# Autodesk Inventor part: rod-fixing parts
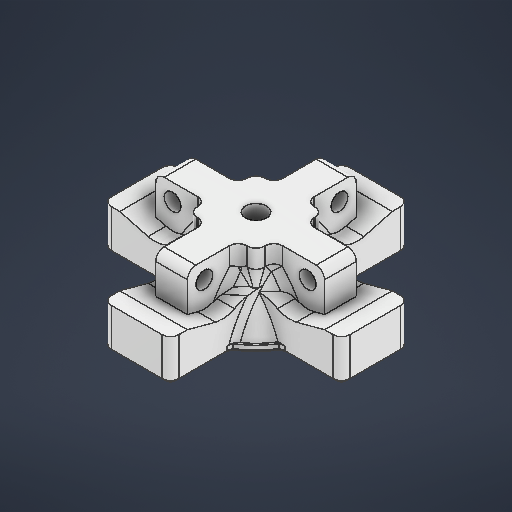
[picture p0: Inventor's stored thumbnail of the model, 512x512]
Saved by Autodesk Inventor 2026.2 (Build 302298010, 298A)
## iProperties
Created: 2026-05
Part Number: rod-fixing parts
Material: ABS 플라스틱
Document SubType Name: Modeling
Designer: work
Density: 1.06 g/cm^3
Appearance: 매끄러움 - 흰색
Author: work
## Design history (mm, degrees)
sketch "스케치1"
  geometry: L1 (-8, 8)-(8, 8); L2 (8, 8)-(8, -8); L3 (8, -8)-(-8, -8); L4 (-8, -8)-(-8, 8); L5 (-8, 8)-(8, -8); L6 (8, 8)-(-8, -8); L7 (-3.75, 20)-(3.75, 20); L8 (3.75, 20)-(3.75, -20); L9 (3.75, -20)-(-3.75, -20); L10 (-3.75, -20)-(-3.75, 20); L11 (-3.75, 20)-(3.75, -20); L12 (3.75, 20)-(-3.75, -20); C1 r 2.5 at (0, 0); 5 further points
  constraints: 24 end point, 4 midpoint, 4 parallel, 2 horizontal, 2 perpendicular, 1 centre point, 1 coincident
  dimensions: "d0" = 16 distance of L2.end L3.end; "d1" = 16 distance of L1.end L2.end; "d2" = 5 diameter of C1; "d3" = 12 distance between parallel lines of L9 L3; "d4" = 7.5 distance of L8.end L9.end
extrude "돌출1" new body sketch "스케치1" distance "d5" = 8; taper "d6" = 0 deg
sketch "스케치2"
  geometry: L1 (0, 0)-(12, 0) reference; L2 (12, 0)-(12, 8) reference; L3 (0, 8)-(12, 8) reference; L4 (0, 0)-(0, 8) reference; L5 (28, 0)-(40, 0) reference; L6 (40, 0)-(40, 8) reference; L7 (28, 8)-(40, 8) reference; L8 (28, 0)-(28, 8) reference; L9 (40, 0)-(40, 8) reference; L10 (40, 4)-(28, 4); L11 (12, 4)-(0, 4); C1 r 2 at (4, 4); C2 r 2 at (36, 4); 1 further point
  constraints: 4 end point, 4 midpoint, 2 centre point, 2 point on line
  dimensions: "d7" = 4 diameter of C2; "d8" = 4 distance from line of L6 C2.centre; "d9" = 4 distance from line of L4 C1.centre; "d10" = 4 diameter of C1
extrude "돌출2" cut sketch "스케치2" extent not by distance; stored distance "d11" = 0; taper "d12" = 0 deg
fillet "모깎기2" dims "d14" = 1
sketch "스케치4"
  geometry: L1 (-1, 8)-(-1, 0) reference; L2 (-12, 8)-(-1, 8) reference; L3 (-12, 0)-(-12, 8) reference; L4 (-12, 0)-(-1, 0) reference; L5 (17, 0)-(17, 8) reference; L6 (17, 0)-(28, 0) reference; L7 (28, 0)-(28, 8) reference; L8 (17, 8)-(28, 8) reference; L9 (5.5, 8)-(10.5, 8) reference; L10 (8, 8)-(8, -6.499); L11 (8, -6.499)-(25.553, -1.796); L12 (25.553, -1.796)-(32.254, 0); L13 (8, 0)-(32.254, 0); L14 (32.254, 0)-(36.254, 0); L15 (36.254, 0)-(36.254, -10); L16 (24, 4)-(24, -10); L17 (24, -10)-(36.254, -10); L18 (0, 0)-(16, 0) reference; L19 (-8, 4)-(-8, -10); L20 (-1, 0)-(-12, 0); L21 (-12, 0)-(-12, 8); L22 (-1, 8)-(-12, 8); L23 (8, 0)-(-16.254, 0); L24 (8, -6.499)-(-9.553, -1.796); L25 (-1, 0)-(-1, 8); L26 (16, 0)-(0, 0); L27 (-16.254, 0)-(-20.254, 0); L28 (-8, -10)-(-20.254, -10); L29 (-20.254, 0)-(-20.254, -10); L30 (-9.553, -1.796)-(-16.254, 0); C1 r 2 at (-8, 4) reference; C2 r 2 at (24, 4) reference; C3 r 6 at (-8, 4); C4 r 2 at (-8, 4); A1 r 6 centre (24, 4) between (25.553, -1.796) and (21.095, -1.25); A2 r 40 centre (7.631, -46.497) between (24, -10) and (8, -6.499); A3 r 10 centre (16.254, -10) between (21.095, -1.25) and (16.254, 0); A4 r 10 centre (-0.254, -10) between (-0.254, 0) and (-5.095, -1.25); A5 r 6 centre (-8, 4) between (-9.553, -1.796) and (-5.095, -1.25); A6 r 40 centre (8.369, -46.497) between (8, -6.499) and (-8, -10); 7 further points
  constraints: 40 end point, 13 symmetric about line, 12 point on circle, 8 centre point, 4 point on line, 3 coincident, 3 perpendicular, 3 tangent, 1 collinear, 1 horizontal, 1 midpoint, 1 vertical, 4 other
  dimensions: "d21" = 12 diameter of C3; "d22" = 12 diameter of A1; "d23" = 75 deg angle of L10 L11; "d24" = 40 radius of A2; "d25" = 4 distance of L12.end L14.end; "d26" = 10 distance between parallel lines of L14 L17; "d27" = 10 radius of A3
extrude "돌출3" join sketch "스케치4" stored distance "d28" = 10; taper "d29" = 0 deg
sketch "스케치5"
  geometry: L1 (-8, 8)-(-4.75, 8) reference; L2 (-3.75, 9)-(-3.75, 20) reference; L3 (-3.75, 20)-(3.75, 20) reference; L4 (3.75, 20)-(3.75, 9) reference; L5 (4.75, 8)-(8, 8) reference; L6 (8, 8)-(8, -8) reference; L7 (8, -8)-(4.75, -8) reference; L8 (3.75, -9)-(3.75, -20) reference; L9 (3.75, -20)-(-3.75, -20) reference; L10 (-3.75, -20)-(-3.75, -9) reference; L11 (-4.75, -8)-(-8, -8) reference; L12 (-8, -8)-(-8, 8) reference; C1 r 2.5 at (0, 0) reference; A1 r 1 centre (-4.75, 9) between (-4.75, 8) and (-3.75, 9) reference; A2 r 1 centre (4.75, 9) between (3.75, 9) and (4.75, 8) reference; A3 r 1 centre (4.75, -9) between (4.75, -8) and (3.75, -9) reference; A4 r 1 centre (-4.75, -9) between (-3.75, -9) and (-4.75, -8) reference; 1 further point
extrude "돌출4" join sketch "스케치5" distance "d30" = 5; taper "d31" = 0 deg
sketch "스케치6"
  geometry: C1 r 6 at (-8, 28.254); 1 further point
  constraints: 1 centre point, 1 coincident
  dimensions: "d32" = 12 diameter of C1
extrude "돌출5" cut sketch "스케치6" distance "d33" = 12; taper "d34" = 0 deg
sketch "스케치7"
  geometry: L1 (8, 2.5)-(8, -2.5) reference; L2 (8, 0)-(-12.782, 0); L3 (-12.782, 0)-(-10, 16); L4 (2, -6)-(2, 6) reference; L5 (2, 6)-(8, 6); L6 (8, 9)-(-0.028, 9) reference; A1 r 40 centre (-46.497, -0.369) between (-6.499, 0) and (-10, 16) reference; A2 r 30 centre (-17.854, -16.491) between (2, 6) and (-8.458, 12); A3 r 32.562 centre (-17.854, -16.491) between (10.722, -0.878) and (-9.568, 15); 2 further points
  constraints: 6 end point, 6 point on circle, 2 centre point, 1 concentric, 1 horizontal, 1 midpoint, 1 parallel
  dimensions: "d35" = 30 radius of A2; "d36" = 12 distance from line of L2 A2.end; "d38" = 3 vertical distance of A2.end A3.end
revolve "회전1" sketch "스케치7" stored, may be unused: angle "d37" = 360 deg
chamfer "모따기3" distance "d41" = 1; stored, may be unused: second distance "d42" = 2, angle "d43" = 45 deg
sketch "스케치8"
  geometry: L1 (7, 8)-(7, -8) reference; L2 (0, 8)-(7, 8) reference; L3 (0, 8)-(0, 8.254) reference; L4 (-1.796, 17.553)-(0, 24.254) reference; L5 (0, 24.254)-(0, 28.254) reference; L6 (0, 28.254)-(-10, 28.254) reference; L7 (-10, 28.254)-(-10, 16) reference; L8 (-10, -16)-(-10, -28.254) reference; L9 (-10, -28.254)-(0, -28.254) reference; L10 (0, -28.254)-(0, -24.254) reference; L11 (0, -24.254)-(-1.796, -17.553) reference; L12 (0, -8.254)-(0, -8) reference; L13 (0, -8)-(7, -8) reference; L14 (7, 0)-(-0.527, 0); L15 (8, -7)-(8, 7) reference; L16 (2, -6)-(2, 6) reference; L17 (8, -2.5)-(2, -2.5) reference; A1 r 30 centre (-17.854, 16.491) between (-8.458, -12) and (2, -6) reference; A2 r 40 centre (-46.497, 0.369) between (-10, -16) and (-7.49, -8.486) reference; A3 r 10 centre (-10, 8.254) between (0, 8.254) and (-1.25, 13.095) reference; A4 r 6 centre (4, 16) between (-1.796, 17.553) and (-1.25, 13.095) reference; A5 r 40 centre (-46.497, -0.369) between (-7.49, 8.486) and (-10, 16) reference; A6 r 40 centre (-46.497, 0.369) between (-10, -16) and (-7.49, -8.486) reference; A7 r 6 centre (4, -16) between (-1.25, -13.095) and (-1.796, -17.553) reference; A8 r 10 centre (-10, -8.254) between (-1.25, -13.095) and (0, -8.254) reference; A9 r 33.426 centre (-17.854, 16.491) between (-10, -16) and (-0.849, -12.287); 6 further points
  constraints: 3 point on circle, 2 end point, 1 centre point, 1 coincident, 1 concentric, 1 midpoint, 1 perpendicular, 5 other
revolve "회전2" sketch "스케치8" stored, may be unused: angle "d44" = 90 deg
fillet "모깎기5" dims "d45" = 2
sketch "스케치9"
  geometry: L1 (0, 9.831)-(0, 0) reference; L2 (-16, 9.831)-(0, 9.831) reference; L3 (-16, 9.831)-(-16, 0) reference; L4 (-2, -2)-(-14, -2) reference; L5 (0, 50.508)-(-16, 50.508) reference; L6 (-2, 54.508)-(-14, 54.508) reference; L7 (-16, 52.508)-(-16, 42.677) reference; L8 (0, 42.677)-(-16, 42.677) reference; L9 (0, 52.508)-(0, 42.677) reference; L10 (-16, 9.831)-(0, 9.831); L11 (0, 9.831)-(0, 42.677); L12 (0, 42.677)-(-16, 42.677); L13 (-16, 42.677)-(-16, 9.831); C1 r 12.904 at (-8, 26.254) reference; C2 r 16 at (-8, 26.254) reference; A1 r 2 centre (-2, 0) between (-2, -2) and (0, 0) reference; A2 r 2 centre (-14, 0) between (-16, 0) and (-14, -2) reference; A3 r 2 centre (-2, 52.508) between (0, 52.508) and (-2, 54.508) reference; A4 r 2 centre (-14, 52.508) between (-14, 54.508) and (-16, 52.508) reference; 15 further points
  constraints: 8 end point, 2 parallel, 1 horizontal, 1 perpendicular, 4 other
extrude "돌출6" join sketch "스케치9" distance "d46" = 2; taper "d47" = 0 deg
sketch "스케치10"
  geometry: C1 r 14 at (6, 28.254); A1 r 16 centre (6, 28.254) between (14.275, 41.948) and (-2.275, 41.948) reference; A2 r 16 centre (6, 28.254) between (-2.275, 41.948) and (-2.275, 14.56) reference; 4 further points
  constraints: 2 coincident, 1 centre point, 3 other
  dimensions: "d48" = 2 radial gap between concentric circles of A1 C1
extrude "돌출7" join sketch "스케치10" distance "d49" = 2; taper "d50" = 0 deg
chamfer "모따기4" distance "d51" = 1; stored, may be unused: second distance "d52" = 2, angle "d53" = 45 deg
fillet "모깎기6" dims "d57" = 2
chamfer "모따기5" distance "d58" = 1; stored, may be unused: second distance "d59" = 2, angle "d60" = 45 deg
node "솔리드1"
pattern_circular "원형 패턴1" dims "d55" = 360 deg
node "투영된 루프1"
node "투영된 루프2"
node "투영된 루프5"
node "투영된 루프6"
node "투영된 루프7"
node "투영된 루프8"
node "투영된 루프9"
node "투영된 루프10"
